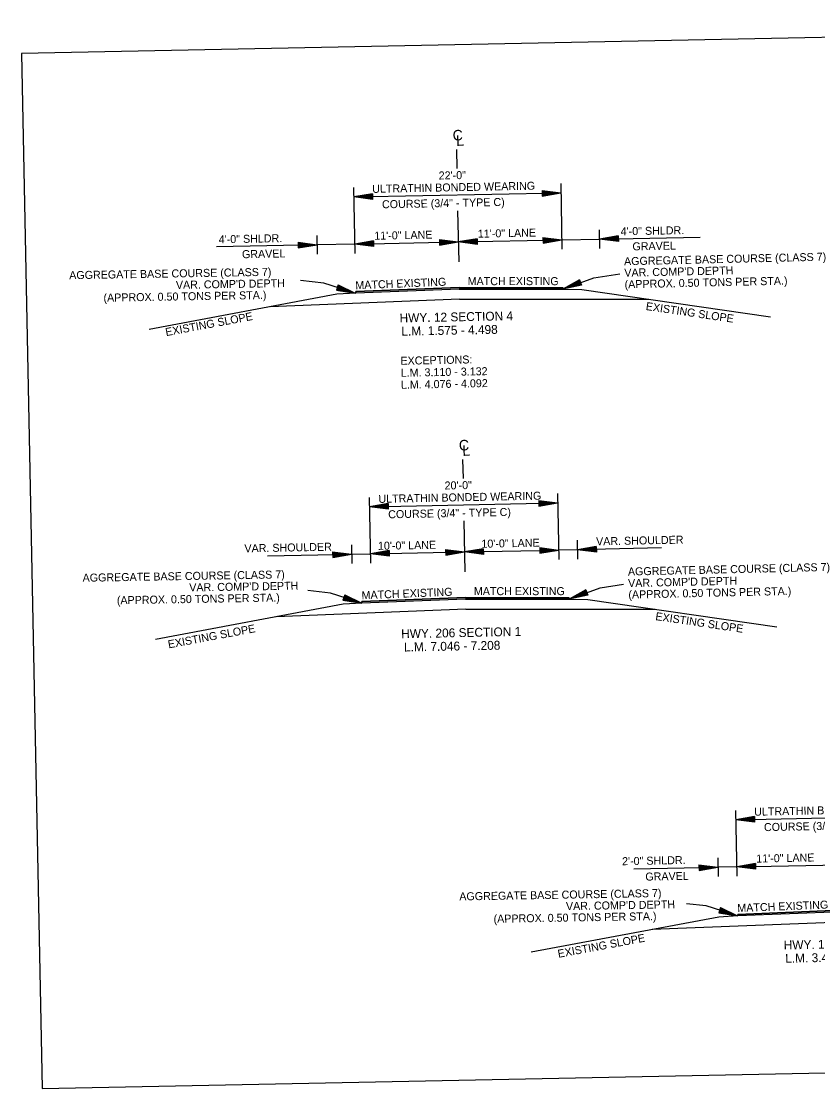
# Model space of a CAD drawing. Extents: x 174 to 869, y -36 to 177.
# Drawn here: x 522.2 to 606.8, y 60.6 to 174 of the extents above; entities that cross this region are included whole.
import ezdxf

# ---------------------------------------------------------------- set-up
doc = ezdxf.new("R2010")
doc.units = 0
for name, color, linetype in [('Default', 7, 'Continuous'), ('DSN_DRFT_Common-Annotations', 7, 'Continuous'), ('DSN_DRFT_Common-Line', 7, 'Continuous'), ('DSN_DRFT_Dimension', 7, 'Continuous')]:
    doc.layers.add(name, color=color, linetype=linetype)

msp = doc.modelspace()

# ---------------------------------------------------------------- linework, layer by layer
at = {"layer": 'Default'}
for p, q in [((554.36, 146.14), (551.88, 146.43)), ((579.76, 145.52), (583.05, 146.71)), ((581.54, 146.48), (579.76, 145.52)), ((581.55, 146.43), (580.07, 145.63)), ((581.57, 146.39), (580.4, 145.75)), ((581.59, 146.34), (580.71, 145.86)), ((581.61, 146.29), (581.03, 145.98)), ((581.54, 146.48), (581.74, 145.92)), ((583.05, 146.71), (585.83, 147.15)), ((557.7, 145.08), (554.36, 146.14)), ((555.89, 145.97), (555.71, 145.4)), ((555.71, 145.4), (557.7, 145.08)), ((555.72, 145.44), (557.38, 145.18)), ((555.74, 145.49), (557.06, 145.28)), ((555.75, 145.54), (556.74, 145.38)), ((555.77, 145.59), (556.42, 145.49)), ((555.78, 145.64), (556.1, 145.59)), ((555.81, 145.73), (556.1, 145.59)), ((555.83, 145.77), (556.42, 145.49)), ((555.84, 145.82), (556.74, 145.38)), ((555.86, 145.87), (557.06, 145.28)), ((555.87, 145.92), (557.38, 145.18)), ((555.89, 145.97), (557.7, 145.08)), ((581.74, 145.92), (579.76, 145.52)), ((581.72, 145.96), (580.07, 145.63)), ((581.71, 146.01), (580.4, 145.75)), ((581.69, 146.06), (580.71, 145.86)), ((581.67, 146.11), (581.03, 145.98)), ((581.62, 146.24), (581.34, 146.09)), ((581.65, 146.15), (581.34, 146.09)), ((555.07, 113.21), (552.69, 113.49)), ((580.42, 112.59), (583.71, 113.78)), ((582.2, 113.55), (580.42, 112.59)), ((582.21, 113.5), (580.73, 112.7)), ((582.23, 113.46), (581.05, 112.82)), ((582.25, 113.41), (581.37, 112.93)), ((582.2, 113.55), (582.4, 112.99)), ((583.71, 113.78), (586.19, 114.17)), ((558.41, 112.15), (555.07, 113.21)), ((556.59, 113.04), (556.41, 112.47)), ((556.41, 112.47), (558.41, 112.15)), ((556.43, 112.52), (558.09, 112.25)), ((556.44, 112.56), (557.76, 112.36)), ((556.46, 112.61), (557.45, 112.46)), ((556.47, 112.66), (557.12, 112.56)), ((556.49, 112.71), (556.8, 112.66)), ((556.52, 112.8), (556.8, 112.66)), ((556.53, 112.85), (557.12, 112.56)), ((556.55, 112.9), (557.45, 112.46)), ((556.56, 112.94), (557.76, 112.36)), ((556.58, 112.99), (558.09, 112.25)), ((556.59, 113.04), (558.41, 112.15)), ((582.4, 112.99), (580.42, 112.59)), ((582.38, 113.03), (580.73, 112.7)), ((582.36, 113.08), (581.05, 112.82)), ((582.35, 113.13), (581.37, 112.93)), ((582.26, 113.36), (581.69, 113.05)), ((582.33, 113.18), (581.69, 113.05)), ((582.28, 113.31), (582, 113.16)), ((582.31, 113.22), (582, 113.16)), ((594.98, 79.98), (592.89, 80.22)), ((598.32, 78.92), (594.98, 79.98)), ((596.5, 79.81), (596.32, 79.24)), ((596.37, 79.38), (597.36, 79.23)), ((596.38, 79.43), (597.03, 79.33)), ((596.4, 79.48), (596.71, 79.43)), ((596.43, 79.57), (596.71, 79.43)), ((596.44, 79.62), (597.03, 79.33)), ((596.46, 79.67), (597.36, 79.23)), ((596.47, 79.71), (597.67, 79.13)), ((596.49, 79.76), (598, 79.02)), ((596.5, 79.81), (598.32, 78.92)), ((596.32, 79.24), (598.32, 78.92)), ((596.34, 79.29), (598, 79.02)), ((596.35, 79.34), (597.67, 79.13))]:
    msp.add_line(p, q, dxfattribs=at)
at = {"layer": 'DSN_DRFT_Common-Line'}
for p, q in [((568.46, 160.35), (568.5, 158.33)), ((579.53, 156.74), (579.67, 149.74)), ((557.54, 156.3), (557.68, 149.3)), ((568.59, 153.81), (568.7, 148.4)), ((553.64, 151.22), (553.68, 149.22)), ((583.63, 151.82), (583.67, 149.82)), ((568.75, 145.69), (557.76, 145.25)), ((568.76, 145.52), (557.76, 145.08)), ((557.76, 145.25), (557.76, 145.08)), ((568.75, 145.69), (579.75, 145.69)), ((568.76, 145.52), (579.76, 145.52)), ((579.75, 145.69), (579.76, 145.52)), ((579.76, 145.52), (581.76, 145.48)), ((581.76, 145.48), (601.82, 142.55)), ((555.76, 144.96), (535.83, 141.23)), ((568.78, 144.44), (548.68, 143.63)), ((557.76, 145.08), (555.76, 144.96)), ((568.78, 144.44), (588.9, 144.44)), ((569.12, 127.42), (569.16, 125.4)), ((579.19, 123.79), (579.33, 116.79)), ((559.2, 123.39), (559.34, 116.39)), ((569.25, 120.88), (569.36, 115.47)), ((557.3, 118.35), (557.34, 116.35)), ((581.29, 118.83), (581.33, 116.83)), ((569.41, 112.76), (558.42, 112.32)), ((569.41, 112.59), (558.42, 112.15)), ((558.42, 112.32), (558.42, 112.15)), ((569.41, 112.76), (580.41, 112.76)), ((569.41, 112.59), (580.42, 112.59)), ((580.41, 112.76), (580.42, 112.59)), ((580.42, 112.59), (582.42, 112.55)), ((582.42, 112.55), (602.48, 109.62)), ((556.42, 112.03), (536.49, 108.3)), ((569.44, 111.51), (549.33, 110.7)), ((558.42, 112.15), (556.42, 112.03)), ((569.44, 111.51), (589.55, 111.51)), ((598.11, 90.14), (598.25, 83.14)), ((596.21, 85.1), (596.25, 83.1)), ((609.32, 79.53), (598.33, 79.09)), ((596.33, 78.8), (576.4, 75.07)), ((609.35, 78.28), (589.25, 77.47)), ((598.33, 78.92), (596.33, 78.8)), ((609.33, 79.36), (598.33, 78.92)), ((598.33, 79.09), (598.33, 78.92))]:
    msp.add_line(p, q, dxfattribs=at)
for points in [[(522.25, 170.55), (524.45, 60.58), (694.42, 63.98), (692.22, 173.95)], [(579.76, 145.52), (568.76, 145.52), (557.76, 145.08), (557.76, 145.25), (568.75, 145.69), (579.75, 145.69)], [(580.42, 112.59), (569.41, 112.59), (558.42, 112.15), (558.42, 112.32), (569.41, 112.76), (580.41, 112.76)], [(620.33, 79.36), (609.33, 79.36), (598.33, 78.92), (598.33, 79.09), (609.32, 79.53), (620.32, 79.53)]]:
    msp.add_lwpolyline(points, close=True, dxfattribs=at)
at = {"layer": 'DSN_DRFT_Dimension'}
for p, q in [((557.56, 155.3), (579.55, 155.74)), ((559.55, 155.64), (557.56, 155.3)), ((559.55, 155.59), (557.89, 155.3)), ((559.55, 155.54), (558.24, 155.31)), ((559.55, 155.49), (558.57, 155.32)), ((559.56, 155.43), (558.91, 155.32)), ((559.56, 155.38), (559.24, 155.33)), ((559.56, 155.29), (559.24, 155.33)), ((559.55, 155.64), (559.56, 155.04)), ((577.55, 156), (579.55, 155.74)), ((577.55, 156), (577.56, 155.4)), ((577.55, 155.95), (579.22, 155.73)), ((577.55, 155.9), (578.88, 155.72)), ((577.55, 155.85), (578.54, 155.72)), ((577.55, 155.79), (578.2, 155.71)), ((577.55, 155.74), (577.87, 155.7)), ((577.55, 155.65), (577.87, 155.7)), ((577.56, 155.4), (579.55, 155.74)), ((577.56, 155.45), (579.22, 155.73)), ((577.56, 155.5), (578.88, 155.72)), ((577.56, 155.55), (578.54, 155.72)), ((577.56, 155.6), (578.2, 155.71)), ((559.56, 155.04), (557.56, 155.3)), ((559.56, 155.09), (557.89, 155.3)), ((559.56, 155.14), (558.24, 155.31)), ((559.56, 155.19), (558.57, 155.32)), ((559.56, 155.24), (558.91, 155.32)), ((570.65, 150.86), (568.66, 150.52)), ((570.65, 150.81), (568.99, 150.52)), ((570.65, 150.86), (570.66, 150.26)), ((577.65, 151), (579.65, 150.74)), ((577.65, 151), (577.66, 150.4)), ((577.65, 150.95), (579.32, 150.73)), ((577.65, 150.9), (578.98, 150.72)), ((577.65, 150.85), (578.64, 150.72)), ((577.65, 150.79), (578.3, 150.71)), ((579.65, 150.74), (583.65, 150.82)), ((585.65, 151.16), (583.65, 150.82)), ((583.65, 150.82), (594.34, 151.03)), ((585.66, 150.56), (583.65, 150.82)), ((585.65, 151.11), (583.99, 150.82)), ((585.66, 150.61), (583.99, 150.82)), ((585.65, 151.06), (584.33, 150.83)), ((585.66, 150.66), (584.33, 150.83)), ((585.65, 151.01), (584.66, 150.84)), ((585.66, 150.71), (584.66, 150.84)), ((585.65, 150.95), (585, 150.84)), ((585.65, 150.76), (585, 150.84)), ((585.65, 150.9), (585.34, 150.85)), ((585.65, 150.81), (585.34, 150.85)), ((585.65, 151.16), (585.66, 150.56)), ((553.66, 150.22), (542.97, 150)), ((551.65, 150.48), (553.66, 150.22)), ((551.65, 150.48), (551.66, 149.88)), ((551.65, 150.43), (553.32, 150.21)), ((551.65, 150.38), (552.98, 150.2)), ((551.66, 150.33), (552.65, 150.2)), ((551.66, 150.27), (552.31, 150.19)), ((551.66, 149.88), (553.66, 150.22)), ((551.66, 150.22), (551.97, 150.18)), ((551.66, 149.93), (553.32, 150.21)), ((551.66, 149.98), (552.98, 150.2)), ((551.66, 150.03), (552.65, 150.2)), ((551.66, 150.08), (552.31, 150.19)), ((551.66, 150.13), (551.97, 150.18)), ((557.66, 150.3), (553.66, 150.22)), ((559.65, 150.64), (557.66, 150.3)), ((557.66, 150.3), (568.66, 150.52)), ((559.66, 150.04), (557.66, 150.3)), ((559.65, 150.59), (557.99, 150.3)), ((559.66, 150.09), (557.99, 150.3)), ((559.65, 150.54), (558.34, 150.31)), ((559.66, 150.14), (558.34, 150.31)), ((559.65, 150.49), (558.67, 150.32)), ((559.66, 150.19), (558.67, 150.32)), ((559.66, 150.43), (559.01, 150.32)), ((559.66, 150.24), (559.01, 150.32)), ((559.66, 150.38), (559.34, 150.33)), ((559.66, 150.29), (559.34, 150.33)), ((559.65, 150.64), (559.66, 150.04)), ((566.65, 150.78), (568.66, 150.52)), ((566.65, 150.78), (566.66, 150.18)), ((566.65, 150.73), (568.32, 150.51)), ((566.65, 150.68), (567.98, 150.5)), ((566.65, 150.63), (567.64, 150.5)), ((566.65, 150.57), (567.31, 150.49)), ((566.65, 150.52), (566.97, 150.48)), ((566.66, 150.18), (568.66, 150.52)), ((566.66, 150.23), (568.32, 150.51)), ((566.66, 150.28), (567.98, 150.5)), ((566.66, 150.33), (567.64, 150.5)), ((566.66, 150.38), (567.31, 150.49)), ((566.66, 150.43), (566.97, 150.48)), ((568.66, 150.52), (579.65, 150.74)), ((570.66, 150.26), (568.66, 150.52)), ((570.66, 150.31), (568.99, 150.52)), ((570.65, 150.76), (569.33, 150.53)), ((570.66, 150.36), (569.33, 150.53)), ((570.65, 150.71), (569.67, 150.54)), ((570.66, 150.41), (569.67, 150.54)), ((570.65, 150.65), (570.01, 150.54)), ((570.66, 150.46), (570.01, 150.54)), ((570.65, 150.6), (570.34, 150.55)), ((570.66, 150.51), (570.34, 150.55)), ((577.65, 150.74), (577.97, 150.7)), ((577.65, 150.65), (577.97, 150.7)), ((577.66, 150.4), (579.65, 150.74)), ((577.66, 150.45), (579.32, 150.73)), ((577.66, 150.5), (578.98, 150.72)), ((577.66, 150.55), (578.64, 150.72)), ((577.66, 150.6), (578.3, 150.71)), ((559.22, 122.39), (579.21, 122.79)), ((561.21, 122.73), (559.22, 122.39)), ((561.21, 122.68), (559.55, 122.39)), ((561.21, 122.63), (559.89, 122.4)), ((561.21, 122.58), (560.23, 122.41)), ((561.21, 122.52), (560.57, 122.41)), ((561.21, 122.47), (560.9, 122.42)), ((561.21, 122.73), (561.22, 122.13)), ((577.21, 123.05), (579.21, 122.79)), ((577.21, 123.05), (577.22, 122.45)), ((577.21, 123), (578.88, 122.78)), ((577.21, 122.95), (578.53, 122.77)), ((577.21, 122.9), (578.2, 122.77)), ((577.21, 122.84), (577.86, 122.76)), ((577.21, 122.79), (577.53, 122.75)), ((577.21, 122.65), (577.86, 122.76)), ((577.21, 122.7), (577.53, 122.75)), ((577.22, 122.45), (579.21, 122.79)), ((577.22, 122.5), (578.88, 122.78)), ((577.22, 122.55), (578.53, 122.77)), ((577.22, 122.6), (578.2, 122.77)), ((561.22, 122.13), (559.22, 122.39)), ((561.22, 122.18), (559.55, 122.39)), ((561.22, 122.23), (559.89, 122.4)), ((561.22, 122.28), (560.23, 122.41)), ((561.22, 122.33), (560.57, 122.41)), ((561.22, 122.38), (560.9, 122.42)), ((571.31, 117.93), (569.31, 117.59)), ((571.31, 117.93), (571.32, 117.33)), ((577.31, 118.05), (579.31, 117.79)), ((577.31, 118.05), (577.32, 117.45)), ((577.31, 118), (578.98, 117.78)), ((577.31, 117.95), (578.63, 117.77)), ((583.31, 118.17), (581.31, 117.83)), ((590.25, 118.01), (581.31, 117.83)), ((583.31, 118.12), (581.65, 117.83)), ((583.31, 118.07), (581.99, 117.84)), ((583.31, 118.02), (582.32, 117.85)), ((583.31, 117.96), (582.66, 117.85)), ((583.31, 117.91), (583, 117.86)), ((583.31, 118.17), (583.32, 117.57)), ((548.38, 117.17), (557.32, 117.35)), ((555.31, 117.61), (557.32, 117.35)), ((555.31, 117.61), (555.32, 117.01)), ((555.31, 117.56), (556.98, 117.34)), ((555.31, 117.51), (556.64, 117.33)), ((555.31, 117.46), (556.31, 117.33)), ((555.31, 117.4), (555.97, 117.32)), ((555.32, 117.01), (557.32, 117.35)), ((555.32, 117.35), (555.63, 117.31)), ((555.32, 117.06), (556.98, 117.34)), ((555.32, 117.11), (556.64, 117.33)), ((555.32, 117.16), (556.31, 117.33)), ((555.32, 117.21), (555.97, 117.32)), ((555.32, 117.26), (555.63, 117.31)), ((557.32, 117.35), (559.32, 117.39)), ((561.31, 117.73), (559.32, 117.39)), ((559.32, 117.39), (569.31, 117.59)), ((561.32, 117.13), (559.32, 117.39)), ((561.31, 117.68), (559.65, 117.39)), ((561.32, 117.18), (559.65, 117.39)), ((561.31, 117.63), (559.99, 117.4)), ((561.32, 117.23), (559.99, 117.4)), ((561.31, 117.58), (560.33, 117.41)), ((561.32, 117.28), (560.33, 117.41)), ((561.31, 117.52), (560.67, 117.41)), ((561.32, 117.33), (560.67, 117.41)), ((561.31, 117.47), (561, 117.42)), ((561.32, 117.38), (561, 117.42)), ((561.31, 117.73), (561.32, 117.13)), ((567.31, 117.85), (569.31, 117.59)), ((567.31, 117.85), (567.32, 117.25)), ((567.31, 117.8), (568.98, 117.58)), ((567.31, 117.75), (568.64, 117.57)), ((567.31, 117.7), (568.3, 117.57)), ((567.31, 117.64), (567.96, 117.56)), ((567.31, 117.59), (567.63, 117.55)), ((567.32, 117.25), (569.31, 117.59)), ((567.32, 117.3), (568.98, 117.58)), ((567.32, 117.35), (568.64, 117.57)), ((567.32, 117.4), (568.3, 117.57)), ((567.32, 117.45), (567.96, 117.56)), ((567.32, 117.5), (567.63, 117.55)), ((569.31, 117.59), (579.31, 117.79)), ((571.32, 117.33), (569.31, 117.59)), ((571.31, 117.88), (569.65, 117.59)), ((571.32, 117.38), (569.65, 117.59)), ((571.31, 117.83), (569.99, 117.6)), ((571.32, 117.43), (569.99, 117.6)), ((571.31, 117.78), (570.32, 117.61)), ((571.32, 117.48), (570.32, 117.61)), ((571.31, 117.72), (570.66, 117.61)), ((571.32, 117.53), (570.66, 117.61)), ((571.31, 117.67), (571, 117.62)), ((571.31, 117.58), (571, 117.62)), ((577.31, 117.9), (578.3, 117.77)), ((577.31, 117.84), (577.96, 117.76)), ((577.31, 117.79), (577.63, 117.75)), ((577.31, 117.65), (577.96, 117.76)), ((577.31, 117.7), (577.63, 117.75)), ((577.32, 117.45), (579.31, 117.79)), ((577.32, 117.5), (578.98, 117.78)), ((577.32, 117.55), (578.63, 117.77)), ((577.32, 117.6), (578.3, 117.77)), ((581.31, 117.83), (579.31, 117.79)), ((583.32, 117.57), (581.31, 117.83)), ((583.32, 117.62), (581.65, 117.83)), ((583.32, 117.67), (581.99, 117.84)), ((583.31, 117.72), (582.32, 117.85)), ((583.31, 117.77), (582.66, 117.85)), ((583.31, 117.82), (583, 117.86)), ((598.13, 89.14), (620.12, 89.58)), ((600.12, 89.48), (598.13, 89.14)), ((600.13, 88.88), (598.13, 89.14)), ((600.12, 89.43), (598.46, 89.14)), ((600.13, 88.93), (598.46, 89.14)), ((600.12, 89.38), (598.81, 89.15)), ((600.13, 88.98), (598.81, 89.15)), ((600.12, 89.33), (599.14, 89.16)), ((600.13, 89.03), (599.14, 89.16)), ((600.13, 89.27), (599.48, 89.16)), ((600.13, 89.08), (599.48, 89.16)), ((600.13, 89.22), (599.81, 89.17)), ((600.13, 89.13), (599.81, 89.17)), ((600.12, 89.48), (600.13, 88.88)), ((587.29, 83.92), (596.23, 84.1)), ((594.22, 84.36), (596.23, 84.1)), ((594.22, 84.36), (594.23, 83.76)), ((594.22, 84.31), (595.89, 84.09)), ((594.22, 84.26), (595.55, 84.08)), ((594.23, 84.21), (595.22, 84.08)), ((594.23, 84.15), (594.88, 84.07)), ((594.23, 83.76), (596.23, 84.1)), ((594.23, 84.1), (594.54, 84.06)), ((594.23, 83.81), (595.89, 84.09)), ((594.23, 83.86), (595.55, 84.08)), ((594.23, 83.91), (595.22, 84.08)), ((594.23, 83.96), (594.88, 84.07)), ((594.23, 84.01), (594.54, 84.06)), ((598.23, 84.14), (596.23, 84.1)), ((600.22, 84.48), (598.23, 84.14)), ((598.23, 84.14), (609.23, 84.36)), ((600.23, 83.88), (598.23, 84.14)), ((600.22, 84.43), (598.56, 84.14)), ((600.23, 83.93), (598.56, 84.14)), ((600.22, 84.38), (598.91, 84.15)), ((600.23, 83.98), (598.91, 84.15)), ((600.22, 84.33), (599.24, 84.16)), ((600.23, 84.03), (599.24, 84.16)), ((600.23, 84.27), (599.58, 84.16)), ((600.23, 84.08), (599.58, 84.16)), ((600.23, 84.22), (599.91, 84.17)), ((600.23, 84.13), (599.91, 84.17)), ((600.22, 84.48), (600.23, 83.88))]:
    msp.add_line(p, q, dxfattribs=at)

# ---------------------------------------------------------------- texts
at = {"layer": 'Default'}
for s, rotation, p in [('AGGREGATE BASE COURSE (CLASS 7)', 1.3198, (586.27, 148.04)), ('AGGREGATE BASE COURSE (CLASS 7)', 0.9717, (527.34, 146.56)), ("VAR. COMP'D DEPTH", 1.3198, (586.3, 146.82)), ("VAR. COMP'D DEPTH", 0.9717, (538.67, 145.53)), ('(APPROX. 0.50 TONS PER STA.)', 1.3198, (586.33, 145.59)), ('(APPROX. 0.50 TONS PER STA.)', 0.9717, (530.98, 144.17)), ('AGGREGATE BASE COURSE (CLASS 7)', 0.9717, (528.76, 114.42)), ('AGGREGATE BASE COURSE (CLASS 7)', 1.3198, (586.68, 115.08)), ("VAR. COMP'D DEPTH", 1.3198, (586.7, 113.85)), ("VAR. COMP'D DEPTH", 0.9717, (540.09, 113.39)), ('(APPROX. 0.50 TONS PER STA.)', 1.3198, (586.73, 112.63)), ('(APPROX. 0.50 TONS PER STA.)', 0.9717, (532.4, 112.03)), ('AGGREGATE BASE COURSE (CLASS 7)', 0.9717, (568.77, 80.57)), ("VAR. COMP'D DEPTH", 0.9717, (580.1, 79.54)), ('(APPROX. 0.50 TONS PER STA.)', 0.9717, (572.41, 78.19))]:
    msp.add_text(s, height=0.85, rotation=rotation, dxfattribs=at).set_placement(p)
at = {"layer": 'DSN_DRFT_Common-Annotations'}
for s, height, rotation, p in [('C', 1.12, 2.2915, (568.08, 161.28)), ('L', 1.12, 2.2915, (568.44, 160.72)), ('22\'-0"', 0.85, 1.1458, (566.58, 157.15)), ('ULTRATHIN BONDED WEARING', 0.85, 1.1458, (559.52, 155.73)), ('COURSE (3/4" - TYPE C)', 0.85, 1.1458, (560.56, 154.09)), ('11\'-0" LANE', 0.85, 1.1458, (570.74, 150.97)), ('4\'-0" SHLDR.', 0.85, 1.1458, (585.91, 151.22)), ('4\'-0" SHLDR.', 0.85, 1.1458, (543.22, 150.37)), ('11\'-0" LANE', 0.85, 1.1458, (559.74, 150.75)), ('GRAVEL', 0.85, 1.1458, (545.69, 148.79)), ('GRAVEL', 0.85, 1.1458, (587.16, 149.62)), ('MATCH EXISTING', 0.85, 2.2915, (557.74, 145.49)), ('EXISTING SLOPE', 0.85, 351.6838, (588.53, 143.3)), ('EXISTING SLOPE', 0.85, 10.6078, (537.63, 140.51)), ('HWY. 12 SECTION 4', 0.943, 1.1458, (562.43, 141.97)), ('L.M. 1.575 - 4.498', 0.943, 1.1458, (562.62, 140.56)), ('EXCEPTIONS:', 0.85, 1.1458, (562.52, 137.47)), ('L.M. 3.110 - 3.132', 0.85, 1.1458, (562.55, 136.19)), ('L.M. 4.076 - 4.092', 0.85, 1.1458, (562.57, 134.92)), ('C', 1.12, 2.2915, (568.74, 128.35)), ('L', 1.12, 2.2915, (569.1, 127.79)), ('20\'-0"', 0.85, 1.1458, (567.21, 124.22)), ('ULTRATHIN BONDED WEARING', 0.85, 1.1458, (560.18, 122.8)), ('COURSE (3/4" - TYPE C)', 0.85, 1.1458, (561.22, 121.16)), ('VAR. SHOULDER', 0.85, 1.1458, (583.3, 118.29)), ('VAR. SHOULDER', 0.85, 1.1458, (545.95, 117.54)), ('10\'-0" LANE', 0.85, 1.1458, (560.13, 117.81)), ('10\'-0" LANE', 0.85, 1.1458, (571.12, 118.03)), ('MATCH EXISTING', 0.85, 2.2915, (558.4, 112.56)), ('EXISTING SLOPE', 0.85, 351.6838, (589.55, 110.36)), ('EXISTING SLOPE', 0.85, 10.6078, (537.9, 107.34)), ('HWY. 206 SECTION 1', 0.943, 1.1458, (562.6, 108.42)), ('L.M. 7.046 - 7.208', 0.943, 1.1458, (562.9, 107.01)), ('ULTRATHIN BONDED WEARING', 0.85, 1.1458, (600.09, 89.57)), ('COURSE (3/4" - TYPE C)', 0.85, 1.1458, (601.13, 87.93)), ('2\'-0" SHLDR.', 0.85, 1.1458, (586.06, 84.31)), ('11\'-0" LANE', 0.85, 1.1458, (600.31, 84.59)), ('GRAVEL', 0.85, 1.1458, (588.53, 82.67)), ('MATCH EXISTING', 0.85, 2.2915, (598.31, 79.33)), ('EXISTING SLOPE', 0.85, 10.6078, (579.3, 74.47)), ('HWY. 16 SECTION 1', 0.943, 1.1458, (603.23, 75.36)), ('L.M. 3.410 - 3.781', 0.943, 1.1458, (603.39, 73.95))]:
    msp.add_text(s, height=height, rotation=rotation, dxfattribs=at).set_placement(p)
for p in [(569.65, 145.93), (570.31, 113)]:
    msp.add_text('MATCH EXISTING', height=0.85, dxfattribs=at).set_placement(p)

doc.saveas('drawing.dxf')
